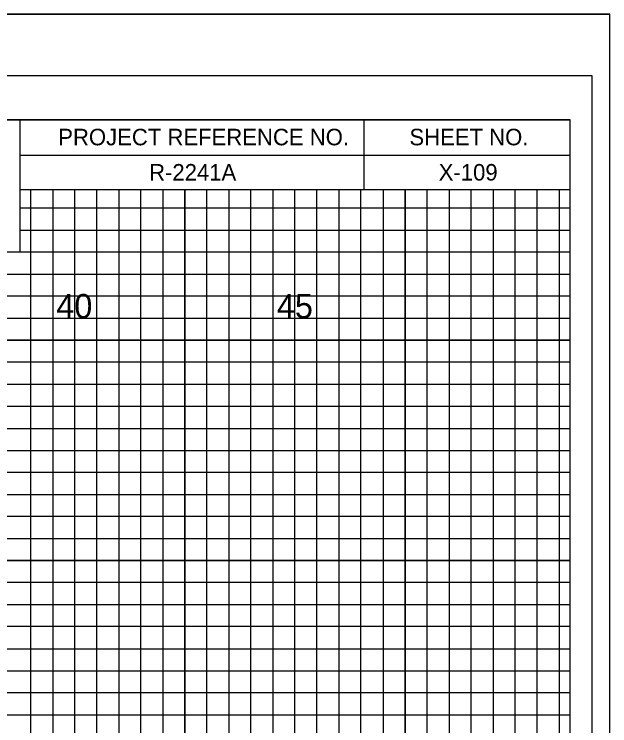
# Model space of a CAD drawing. Extents: x -4 to 103, y -2 to 209.
# Drawn here: x 89.88 to 103.4, y 122.08 to 138.22 of the extents above; entities that cross this region are included whole.
import ezdxf

# ---------------------------------------------------------------- set-up
doc = ezdxf.new("R2010")
doc.units = 0
for name, color, linetype in [('Old_Level_10', 7, 'Continuous'), ('Old_Level_16', 7, 'Continuous'), ('Old_Level_17', 7, 'Continuous'), ('Old_Level_3', 7, 'Continuous'), ('Old_Level_5', 7, 'Continuous'), ('Old_Level_6', 7, 'Continuous'), ('Old_Level_8', 7, 'Continuous'), ('Prop Plan Preparation Sketches Hydraulic Ditch', 7, 'Continuous'), ('Prop XS SE Text', 7, 'Continuous'), ('Typical Curb CELL', 7, 'Continuous')]:
    doc.layers.add(name, color=color, linetype=linetype)

msp = doc.modelspace()

# ---------------------------------------------------------------- linework, layer by layer
at = {"layer": 'Old_Level_10'}
for p, q in [((91.25, 70.825), (91.25, 134.25)), ((93.75, 70.825), (93.75, 134.25)), ((96.25, 70.825), (96.25, 134.25)), ((98.75, 70.825), (98.75, 134.25)), ((101.25, 70.825), (101.25, 134.25)), ((90, 133.325), (102.5, 133.325)), ((0, 130.825), (102.5, 130.825)), ((0, 128.325), (102.5, 128.325)), ((0, 125.825), (102.5, 125.825)), ((0, 123.325), (102.5, 123.325))]:
    msp.add_line(p, q, dxfattribs=at)
at = {"layer": 'Old_Level_17'}
for points in [[(90.25, 70.825), (90.25, 134.25), (90.75, 134.25), (90.75, 70.825)], [(91.75, 70.825), (91.75, 134.25), (92.25, 134.25), (92.25, 70.825)], [(92.75, 70.825), (92.75, 134.25), (93.25, 134.25), (93.25, 70.825)], [(94.25, 70.825), (94.25, 134.25), (94.75, 134.25), (94.75, 70.825)], [(95.25, 70.825), (95.25, 134.25), (95.75, 134.25), (95.75, 70.825)], [(96.75, 70.825), (96.75, 134.25), (97.25, 134.25), (97.25, 70.825)], [(97.75, 70.825), (97.75, 134.25), (98.25, 134.25), (98.25, 70.825)], [(99.25, 70.825), (99.25, 134.25), (99.75, 134.25), (99.75, 70.825)], [(100.25, 70.825), (100.25, 134.25)], [(100.25, 134.25), (100.75, 134.25), (100.75, 70.825), (101.75, 70.825), (101.75, 134.25), (102.25, 134.25), (102.25, 70.825)], [(102.5, 132.825), (102.5, 133.825), (90, 133.825)], [(0, 132.325), (102.5, 132.325), (102.5, 132.825), (0, 132.825)], [(0, 131.325), (102.5, 131.325), (102.5, 131.825), (0, 131.825)], [(0, 129.825), (102.5, 129.825), (102.5, 130.325), (0, 130.325)], [(0, 128.825), (102.5, 128.825), (102.5, 129.325), (0, 129.325)], [(0, 127.325), (102.5, 127.325), (102.5, 127.825), (0, 127.825)], [(0, 126.325), (102.5, 126.325), (102.5, 126.825), (0, 126.825)], [(0, 124.825), (102.5, 124.825), (102.5, 125.325), (0, 125.325)], [(0, 123.825), (102.5, 123.825), (102.5, 124.325), (0, 124.325)], [(0, 122.325), (102.5, 122.325), (102.5, 122.825), (0, 122.825)]]:
    msp.add_lwpolyline(points, dxfattribs=at)
at = {"layer": 'Old_Level_3'}
msp.add_line((-3.5, 138.225), (103.4, 138.225), dxfattribs=at)
at = {"layer": 'Old_Level_5'}
msp.add_lwpolyline([(103.4, 138.225), (-3.5, 138.225), (-3.5, 68.4), (103.4, 68.4)], close=True, dxfattribs=at)
at = {"layer": 'Old_Level_6'}
for p, q in [((90, 135.825), (102.5, 135.825)), ((90, 135.825), (102.5, 135.825)), ((97.825, 134.25), (97.825, 135.825)), ((101.875, 135.825), (101.875, 135.825)), ((102.5, 135.825), (102.5, 135.825)), ((102.5, 134.25), (102.5, 135.825)), ((102.5, 135.825), (102.5, 135.825)), ((102.5, 135.825), (102.5, 135.825)), ((102.5, 134.25), (102.5, 135.825)), ((90, 135.025), (102.5, 135.025)), ((90, 134.25), (102.5, 134.25)), ((99.4, 134.25), (99.4, 134.25)), ((99.4, 134.25), (99.4, 134.25))]:
    msp.add_line(p, q, dxfattribs=at)
for points in [[(102.5, 135.825), (0, 135.825), (0, 70.825), (102.5, 70.825)], [(83.75, 135.825), (90, 135.825), (90, 132.825), (83.75, 132.825)]]:
    msp.add_lwpolyline(points, close=True, dxfattribs=at)
at = {"layer": 'Old_Level_8'}
for points in [[(91.25, 70.825), (91.25, 134.25), (93.75, 134.25), (93.75, 70.825)], [(96.25, 70.825), (96.25, 134.25), (98.75, 134.25), (98.75, 70.825)], [(101.25, 70.825), (101.25, 134.25)], [(90, 133.325), (102.5, 133.325)], [(0, 128.325), (102.5, 128.325), (102.5, 130.825), (0, 130.825)], [(0, 123.325), (102.5, 123.325), (102.5, 125.825), (0, 125.825)]]:
    msp.add_lwpolyline(points, dxfattribs=at)
at = {"layer": 'Typical Curb CELL'}
msp.add_lwpolyline([(103, 136.825), (-2.8, 136.825), (-2.8, 69.825), (103, 69.825)], close=True, dxfattribs=at)

# ---------------------------------------------------------------- texts
at = {"layer": 'Old_Level_16'}
for s, p in [('40', (90.8313, 131.325)), ('45', (95.8399, 131.325))]:
    msp.add_text(s, height=0.55, dxfattribs=at).set_placement(p)
at = {"layer": 'Old_Level_6'}
for s, p in [('PROJECT REFERENCE NO.', (90.875, 135.25)), ('SHEET NO.', (98.85, 135.25))]:
    msp.add_text(s, height=0.375, dxfattribs=at).set_placement(p)
at = {"layer": 'Prop Plan Preparation Sketches Hydraulic Ditch'}
msp.add_text('X-109', height=0.375, dxfattribs=at).set_placement((99.5152, 134.45))
at = {"layer": 'Prop XS SE Text'}
msp.add_text('R-2241A', height=0.375, dxfattribs=at).set_placement((92.9378, 134.45))

doc.saveas('drawing.dxf')
